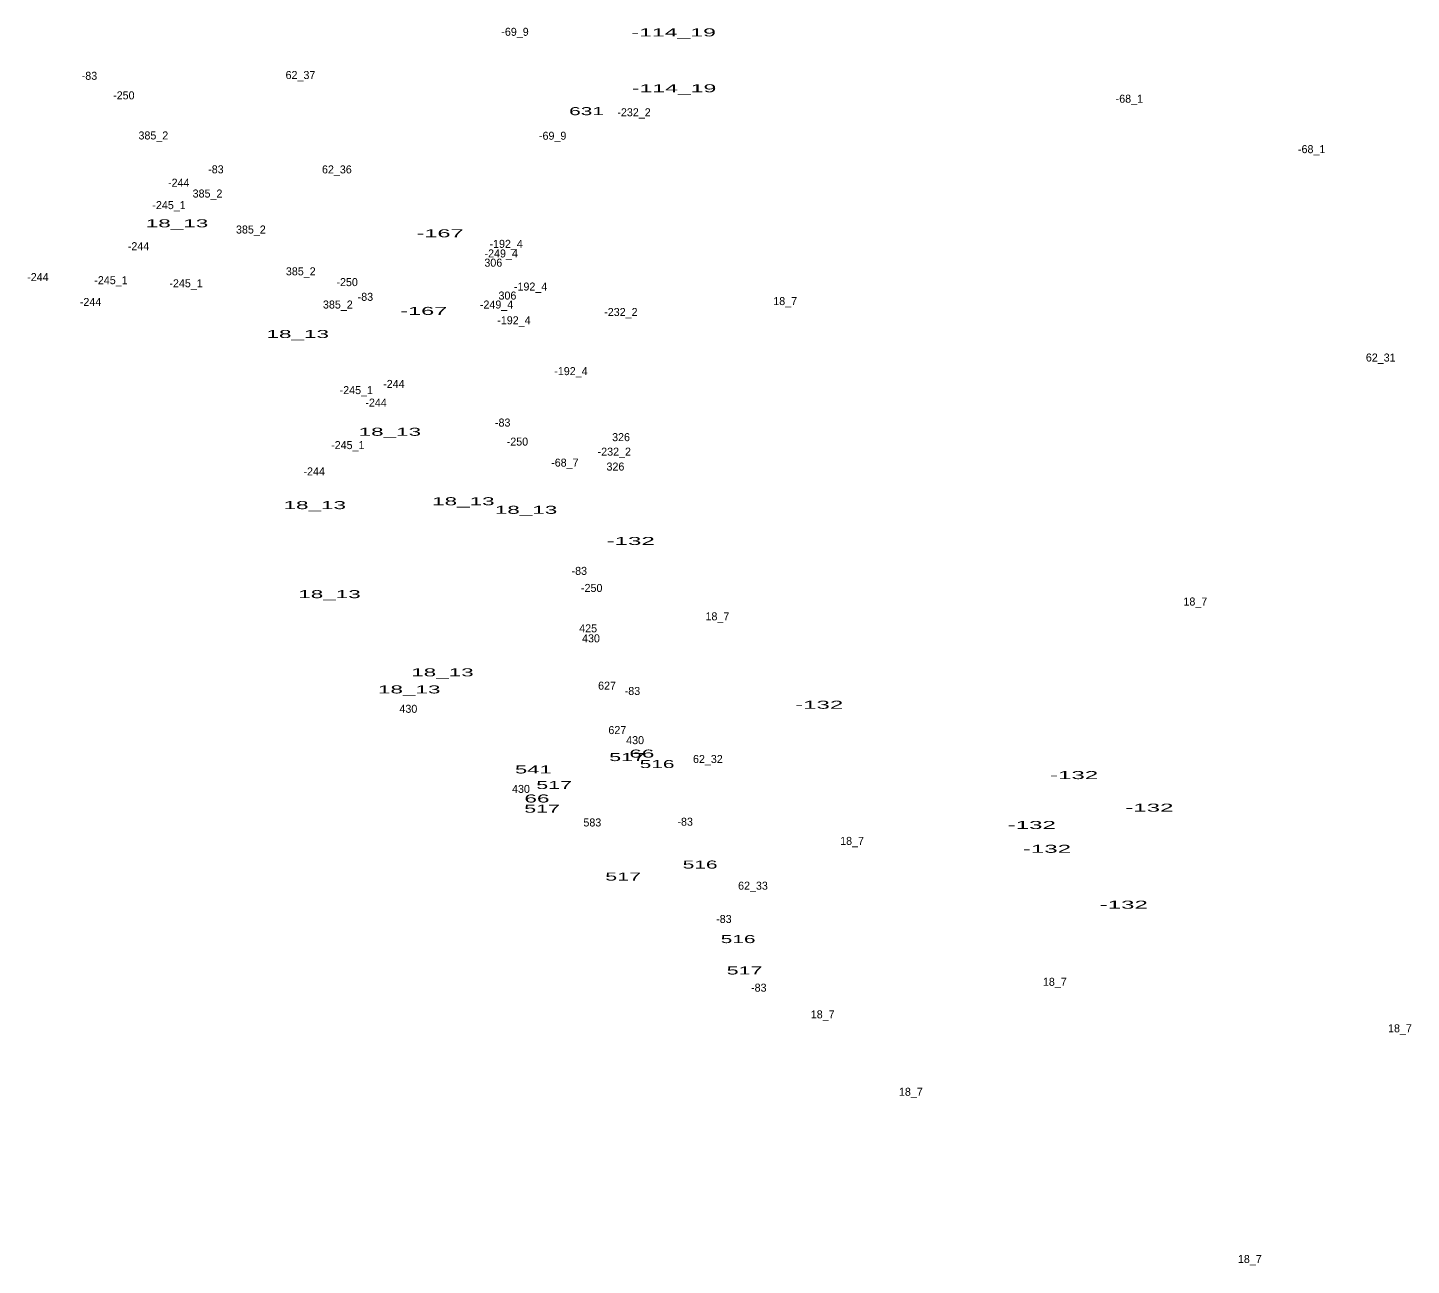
# Model space of a CAD drawing. Extents: x -661742 to -657295, y -1002932 to -996888.
# Drawn here: x -661178 to -660486, y -1002643 to -1002025 of the extents above; entities that cross this region are included whole.
import ezdxf
from ezdxf.enums import TextEntityAlignment as Align

# ---------------------------------------------------------------- set-up
doc = ezdxf.new("R2010")
doc.units = 0
doc.header["$LTSCALE"] = 1.6
doc.layers.add('24', color=7, linetype='Continuous')

msp = doc.modelspace()

# ---------------------------------------------------------------- texts
at = {"layer": '24'}
for s, p in [('-69_9', (-660934.388, -1002028.98)), ('-83', (-661147.095, -1002050.97)), ('62_37', (-661041.626, -1002050.57)), ('-250', (-661129.909, -1002060.74)), ('-68_1', (-660627.322, -1002062.42)), ('-232_2', (-660874.902, -1002069.19)), ('385_2', (-661115.155, -1002080.78)), ('-69_9', (-660915.578, -1002080.93)), ('-68_1', (-660536.202, -1002087.63)), ('-83', (-661083.895, -1002097.7)), ('62_36', (-661023.426, -1002097.76)), ('-244', (-661102.463, -1002104.4)), ('385_2', (-661088.085, -1002109.8)), ('-245_1', (-661107.33, -1002115.58)), ('385_2', (-661066.415, -1002127.79)), ('-244', (-661122.583, -1002136.13)), ('-192_4', (-660938.816, -1002134.95)), ('306', (-660945.237, -1002144.36)), ('-249_4', (-660941.296, -1002139.74)), ('-244', (-661172.863, -1002151.56)), ('385_2', (-661041.475, -1002148.68)), ('-245_1', (-661136.34, -1002153.11)), ('-245_1', (-661098.82, -1002154.66)), ('-250', (-661018.289, -1002154.08)), ('-192_4', (-660926.606, -1002156.29)), ('-244', (-661146.563, -1002163.99)), ('385_2', (-661022.945, -1002165.28)), ('-83', (-661009.175, -1002161.43)), ('-249_4', (-660943.616, -1002165.28)), ('306', (-660938.177, -1002160.8)), ('18_7', (-660799.344, -1002163.56)), ('-192_4', (-660934.936, -1002173.16)), ('-232_2', (-660881.482, -1002169.03)), ('62_31', (-660501.674, -1002191.77)), ('-192_4', (-660906.436, -1002198.56)), ('-244', (-660994.933, -1002204.96)), ('-245_1', (-661013.72, -1002208.05)), ('-244', (-661003.833, -1002214.29)), ('-83', (-660940.545, -1002224.27)), ('-245_1', (-661017.98, -1002235.53)), ('-250', (-660933.189, -1002233.79)), ('326', (-660881.393, -1002231.55)), ('-232_2', (-660884.772, -1002238.81)), ('-244', (-661034.773, -1002248.68)), ('-68_7', (-660909.484, -1002244.28)), ('326', (-660884.203, -1002246.26)), ('-83', (-660902.255, -1002298.39)), ('-250', (-660896.059, -1002306.92)), ('18_7', (-660594.334, -1002313.7)), ('18_7', (-660833.224, -1002321.12)), ('425', (-660897.831, -1002327.09)), ('430', (-660896.415, -1002332.1)), ('627', (-660888.398, -1002355.75)), ('-83', (-660875.695, -1002358.4)), ('430', (-660987.695, -1002367.31)), ('627', (-660883.258, -1002377.95)), ('430', (-660874.365, -1002382.98)), ('62_32', (-660837.99, -1002392.41)), ('430', (-660931.415, -1002407.36)), ('583', (-660895.737, -1002424.12)), ('-83', (-660849.335, -1002423.75)), ('18_7', (-660765.924, -1002433.34)), ('62_33', (-660815.45, -1002455.72)), ('-83', (-660829.985, -1002472.35)), ('18_7', (-660664.574, -1002503.76)), ('-83', (-660812.535, -1002506.68)), ('18_7', (-660780.614, -1002520.01)), ('18_7', (-660492.064, -1002526.98)), ('18_7', (-660736.524, -1002558.71)), ('18_7', (-660567.104, -1002642.29))]:
    msp.add_text(s, height=4, dxfattribs=at).set_placement(p, align=Align.CENTER)
for s, width, p in [('-114_19', 2.15, (-660855.085, -1002029.28)), ('-114_19', 2.15, (-660854.895, -1002057.21)), ('631', 1.95, (-660898.643, -1002068.64)), ('18_13', 2.1, (-661103.325, -1002124.68)), ('-167', 2.2, (-660971.849, -1002129.68)), ('-167', 2.2, (-660979.989, -1002168.47)), ('18_13', 2.1, (-661042.985, -1002180.01)), ('18_13', 2.1, (-660996.955, -1002228.86)), ('18_13', 2.1, (-661034.475, -1002265.52)), ('18_13', 2.1, (-660960.215, -1002263.59)), ('18_13', 2.1, (-660928.875, -1002267.88)), ('-132', 2.25, (-660876.571, -1002283.44)), ('18_13', 2.1, (-661027.125, -1002310.02)), ('18_13', 2.1, (-660970.655, -1002349.1)), ('18_13', 2.1, (-660987.285, -1002357.63)), ('-132', 2.25, (-660782.351, -1002365.29)), ('517', 2, (-660878.383, -1002391.44)), ('66', 2.1, (-660870.991, -1002389.7)), ('541', 2.05, (-660925.243, -1002397.64)), ('516', 1.95, (-660863.383, -1002394.93)), ('-132', 2.25, (-660654.941, -1002400.44)), ('517', 2, (-660914.833, -1002405.41)), ('66', 2.1, (-660923.411, -1002412.14)), ('517', 2, (-660920.853, -1002417.23)), ('-132', 2.25, (-660617.331, -1002416.73)), ('-132', 2.25, (-660676.111, -1002425.38)), ('-132', 2.25, (-660668.511, -1002437.29)), ('516', 1.95, (-660841.863, -1002445.16)), ('517', 2, (-660880.333, -1002451.17)), ('-132', 2.25, (-660630.121, -1002465.22)), ('516', 1.95, (-660822.863, -1002482.4)), ('517', 2, (-660819.653, -1002498.1))]:
    msp.add_text(s, height=4, dxfattribs=dict(at, width=width)).set_placement(p, align=Align.CENTER)

doc.saveas('drawing.dxf')
